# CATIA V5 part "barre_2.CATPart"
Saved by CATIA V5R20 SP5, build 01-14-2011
Part number: barre_2
Publications: "diamètre pivot", "diamètre pivot en E"
Bounding box of the stored display mesh (mm): x 6 to 18, y -135.242 to -6.347, z 15.371 to 84.517
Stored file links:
  E:\IAO_2010\iao\IAO_MMS_Groupe2\IAO_MMS_Groupe2\OK\sdubois\sdubois\sdubois\IAO_mecanisme\barre_2.CATPart
  E:\IAO_2010\iao\IAO_MMS_Groupe2\IAO_MMS_Groupe2\OK\sdubois\sdubois\sdubois\IAO_mecanisme\assembage final.CATProduct
  E:\IAO_2010\iao\IAO_MMS_Groupe2\IAO_MMS_Groupe2\OK\sdubois\sdubois\sdubois\IAO_mecanisme\squelette_2.CATPart
  E:\IAO_2010\iao\IAO_MMS_Groupe2\IAO_MMS_Groupe2\OK\sdubois\sdubois\sdubois\IAO_mecanisme\squelette_4.CATPart
  E:\IAO_2010\iao\IAO_MMS_Groupe2\IAO_MMS_Groupe2\OK\sdubois\sdubois\sdubois\IAO_mecanisme\roue_1.CATPart
  E:\IAO_2010\iao\IAO_MMS_Groupe2\IAO_MMS_Groupe2\OK\sdubois\sdubois\sdubois\IAO_mecanisme\barre_7.CATPart
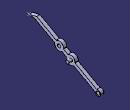
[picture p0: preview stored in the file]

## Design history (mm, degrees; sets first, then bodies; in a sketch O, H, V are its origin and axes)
Parameters
  `diamètre pivot en C` = 6 mm
  `diamètre pivot en E` = 6 mm
External parameters (linked from other documents)
  External.largeur_barre = 6 mm
  `External.diamètre pivot en B` = 6 mm
  External.largeur_barre_7 = 6 mm
Set1
  Plane1: linked copy from another document
  Point1 to Point6: linked copy from another document
  Line1: linked copy from another document
  Plane2: linked copy from another document
  Plane3: linked copy from another document
Set2
  Point7: (0, 0, 0), relative to vertex [face of Pad1 from Sketch1.L4 | face of Pad1 from Sketch1.L3 | face of Pad4]
Body1 (main body)
  Sketch1 on Plane1, origin (6, 0, 0), H (0, 1, 0), V (0, 0, 1)
    line L1 (-122.1466, 84.5175) -> (-9.9048, 22.9888)
    point P1 (-122.1466, 84.5175)
    point P2 (-9.9048, 22.9888)
    line L2 (-125.0308, 79.2561) -> (-12.789, 17.7275)
    point P3 (-125.0308, 79.2561)
    point P4 (-12.789, 17.7275)
    line L3 (-135.2418, 81.4324) -> (-122.1466, 84.5175)
    point P5 (-135.2418, 81.4324)
    point P6 (-122.1466, 84.5175)
    line L4 (-135.2418, 81.4324) -> (-125.0308, 79.2561)
    point P7 (-135.2418, 81.4324)
    point P8 (-125.0308, 79.2561)
    reference projected point E1 (-122.1466, 84.5175) from Point4
    reference projected point E2 (-122.1466, 84.5175) from Point4
    reference projected point E3 (-135.2418, 81.4324) from Point6
    reference projected point E4 (-135.2418, 81.4324) from Point6
    reference projected point E5 (-125.0308, 79.2561) from Point5
    reference projected point E6 (-125.0308, 79.2561) from Point5
    reference projected line E7 (-91.9488, 64.5424) -> (-70.9034, 53.0058) from Line1
    reference projected line E8 (-91.9488, 64.5424) -> (-70.9034, 53.0058) from Line1
    reference intersected line E9 through (-21.4154, 1.9911) direction (0.4807, 0.8769) from Plane2
    reference intersected line E10 through (-21.4154, 1.9911) direction (0.4807, 0.8769) from Plane2
    line L5 (-9.9048, 22.9888) -> (-12.789, 17.7275)
    point P9 (-9.9048, 22.9888)
    point P10 (-12.789, 17.7275)
    distance P1 E1 = 0
    distance P6 E2 = 0
    distance P5 E3 = 0
    distance P7 E4 = 0
    distance P8 E5 = 0
    distance P3 E6 = 0
    distance P2 E9 = 0
    distance P4 E10 = 0
    distance P9 P2 = 0
    distance P10 P4 = 0
    parallelism: L1 E7, L2 E8
  Sketch2 on Plane1, origin (6, 0, 0), H (0, 1, 0), V (0, 0, 1)
    circle A1 centre (-81.498, 58.8136) radius 8
    point P1 (-81.498, 58.8136)
    reference projected point E1 (-81.498, 58.8136) from Point3
    distance P1 E1 = 0
    radius A1 = 8
  Sketch3 on Plane1, origin (6, 0, 0), H (0, 1, 0), V (0, 0, 1)
    circle A1 centre (-60.4527, 47.2769) radius 8
    point P1 (-60.4527, 47.2769)
    reference projected point E1 (-60.4527, 47.2769) from Point2
    distance P1 E1 = 0
    radius A1 = 8
  Sketch4 on Plane1, origin (6, 0, 0), H (0, 1, 0), V (0, 0, 1)
    circle A1 centre (-11.3469, 20.3582) radius 5
    point P1 (-11.3469, 20.3582)
    reference projected point E1 (-11.3469, 20.3582) from Point1
    distance E1 P1 = 0
    radius A1 = 5
  Sketch5 on Plane1, origin (6, 0, 0), H (0, 1, 0), V (0, 0, 1)
    circle A1 centre (-81.498, 58.8136) radius 3
    point P1 (-81.498, 58.8136)
    reference projected point E1 (-81.498, 58.8136) from Point3
    distance E1 P1 = 0
    radius A1 = 3 {= `diamètre pivot en C` /2}
  Sketch6 on Plane1, origin (6, 0, 0), H (0, 1, 0), V (0, 0, 1)
    circle A1 centre (-60.4527, 47.2769) radius 3
    point P1 (-60.4527, 47.2769)
    reference projected point E1 (-60.4527, 47.2769) from Point2
    distance E1 P1 = 0
    radius A1 = 3 {= `diamètre pivot en E` /2}
  Sketch7 on Plane1, origin (6, 0, 0), H (0, 1, 0), V (0, 0, 1)
    circle A1 centre (-11.3469, 20.3582) radius 3
    point P1 (-11.3469, 20.3582)
    reference projected point E1 (-11.3469, 20.3582) from Point1
    distance E1 P1 = 0
    radius A1 = 3 {= `External.diamètre pivot en B` /2}
  Pad1: profile Sketch1, direction (1, 0, 0), length 6 {= 2*External.largeur_barre_7   -6mm}, opposite side length 0 {= 6mm-External.largeur_barre}
  Pad2: profile Sketch2, direction (1, 0, 0), length 6 {= 2*External.largeur_barre -6mm}, opposite side length 0 {= 6mm-External.largeur_barre}
  Pad3: profile Sketch3, direction (1, 0, 0), length 6 {= 2*External.largeur_barre -6mm}, opposite side length 0 {= 6mm-External.largeur_barre}
  Pad4: profile Sketch4, direction (1, 0, 0), length 6 {= 2*External.largeur_barre -6mm}, opposite side length 0 {= 6mm-External.largeur_barre}
  Pocket1: profile Sketch5, direction (1, 0, 0), length 6 {= 2*External.largeur_barre -6mm}, opposite side length 0 {= 6mm-External.largeur_barre}
  Pocket2: profile Sketch7, direction (1, 0, 0), length 6 {= 2*External.largeur_barre -6mm}, opposite side length 0 {= 6mm-External.largeur_barre}
  Pad5: profile Sketch6, direction (1, 0, 0), length 12 {= 3*External.largeur_barre -6mm}, opposite side length 0 {= 6mm-External.largeur_barre}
